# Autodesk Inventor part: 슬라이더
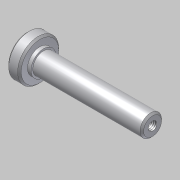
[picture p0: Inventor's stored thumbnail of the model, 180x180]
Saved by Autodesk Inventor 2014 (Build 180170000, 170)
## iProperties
Created: 2011-04
Part Number: 슬라이더
Document SubType Name: Modeling
Designer: 한국산업디자인학원 [http://gmhk.co.kr]
Density: 1 g/cm^3
Material: 일반
Appearance: 기본값
Mass: 9.77098 g
Surface Area: 38.1769 cm^2
Volume: 9.77098 cm^3
Author: pww
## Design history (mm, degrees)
sketch "스케치1"
  geometry: L1 (-7, 0)-(63, 0); L2 (63, 0)-(63, 6); L3 (63, 6)-(0, 6); L4 (-7, 0)-(-7, 11.5); L5 (-7, 11.5)-(0, 11.5); L6 (0, 11.5)-(0, 6); 1 further point
  constraints: 12 end point, 3 perpendicular, 2 horizontal, 2 point on line, 1 parallel
  dimensions: "d1" = 70 distance of L1.start L1.end; "d19" = 12 diameter of L3 L1; "d20" = 7 distance of L4.end L5.end; "d21" = 23 diameter of L5 L1
revolve "회전1" stored, may be unused: angle "d4" = 90 deg
chamfer "모따기1" distance "d16" = 1; stored, may be unused: second distance "d17" = 2, angle "d18" = 45 deg
hole "구멍2" diameter "d24" = 4.917; stored, may be unused: countersink angle "d28" = 90 deg, drill point angle "d30" = 118 deg; dims "d22" = 10, "d23" = 10, "d25" = 10, "d26" = 4, "d27" = 2, "d29" = 13
sketch "스케치2"
  geometry: C1 r 7 at (0, 0); 1 further point
  constraints: 1 centre point, 1 coincident
  dimensions: "d31" = 14 diameter of C1
extrude "돌출2" join sketch "스케치2" distance "d32" = 2; taper "d33" = 0 deg
node "솔리드1"
